// TIA Portal project "ClipX_Profinet" (V13)

(* hardware
DEVICE "S7300/ET200M station_1"  S7-300 station
   slot 0: "Rail_0"  Rail  6ES7 390-1***0-0AA0
   slot 2: "PLC_1"  CPU 315-2 PN/DP  6ES7 315-2EH14-0AB0  V3.2
      slot 2: "PROFINET interface_1"  PN-IO
         slot 1: "Port_1"  Port
         slot 2: "Port_2"  Port
DEVICE "GSD device_1"  GSD.Device.PN
   slot 0: "Rack"  Rail  V1.0
   slot 0: "ClipX"  BMxx
*)

// ===== PLC "PLC_1"  CPU 315-2 PN/DP =====

ORGANIZATION_BLOCK "Main"   // OB1, LAD
TITLE = "Main Program Sweep (Cycle)"
{ S7_Optimized_Access := 'FALSE' }
VERSION : 0.1
BEGIN
END_ORGANIZATION_BLOCK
